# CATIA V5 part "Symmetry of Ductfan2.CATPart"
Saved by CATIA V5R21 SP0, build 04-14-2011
Part number: Symmetry of Ductfan2
Bounding box of the stored display mesh (mm): x -394.667 to 344.98, y -360 to 40, z -344.802 to 344.802
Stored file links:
  C:\Users\rodri\OneDrive\Área de Trabalho\FACULDADE\3°semestre\Sistemas Aeroespaciais\Projeto de avião 2019-02\CAD\Symmetry of Ductfan2.CATPart
  C:\Users\rodri\OneDrive\Área de Trabalho\FACULDADE\3°semestre\Sistemas Aeroespaciais\Projeto de avião 2019-02\CAD\Ductfan completo2.CATPart
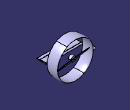
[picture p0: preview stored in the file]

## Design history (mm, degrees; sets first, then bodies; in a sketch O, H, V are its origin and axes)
Body1 (main body)
  Body2 "Body from original PartBody"
    Solid1: linked copy from another document
  Assemble1: tool Body2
